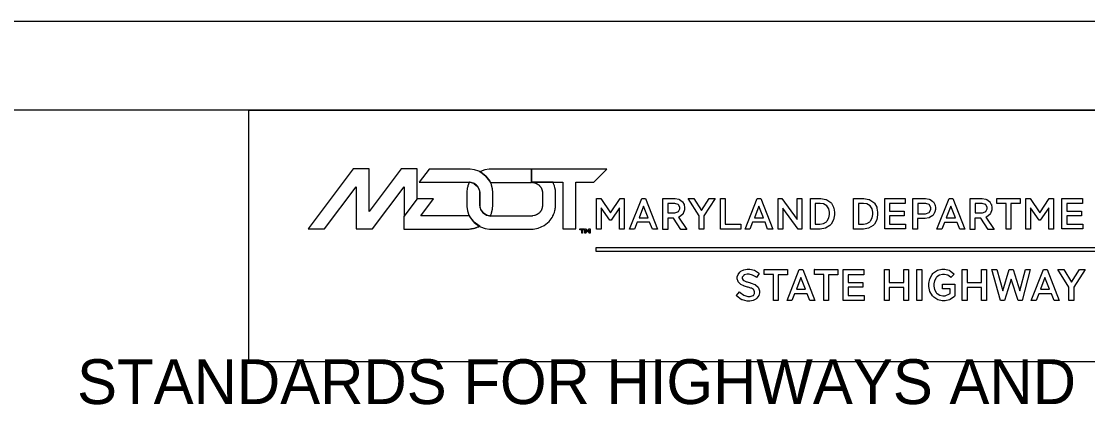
# Model space of a CAD drawing. Extents: x -0.5 to 19.9, y 5.2 to 17.3.
# Drawn here: x 15.428 to 17.634, y 6.826 to 7.619 of the extents above; entities that cross this region are included whole.
import ezdxf

# ---------------------------------------------------------------- set-up
doc = ezdxf.new("R2010")
doc.units = 0
for name, color, linetype in [('BORD-LINE', 7, 'Continuous'), ('MSHA-LOGO', 7, 'Continuous'), ('TTLB-TEXT', 7, 'Continuous'), ('USER-LINE', 7, 'Continuous')]:
    doc.layers.add(name, color=color, linetype=linetype)

msp = doc.modelspace()

# ---------------------------------------------------------------- linework, layer by layer
at = {"layer": 'BORD-LINE'}
for p, q in [((19.6208, 7.6193), (12.2466, 7.6193)), ((19.6208, 7.4352), (15.1479, 7.4352))]:
    msp.add_line(p, q, dxfattribs=at)
at = {"layer": 'MSHA-LOGO'}
for points in [[(16.2199, 7.2152), (16.247, 7.2513), (16.247, 7.314), (16.214, 7.314), (16.1936, 7.2866), (16.1478, 7.2255), (16.1478, 7.314), (16.1148, 7.314), (16.0216, 7.1897), (16.0556, 7.1897), (16.1206, 7.2765), (16.1206, 7.1897), (16.1548, 7.1897), (16.2199, 7.2765)], [(16.355, 7.2861), (16.3558, 7.2861), (16.3634, 7.2841), (16.3641, 7.2837), (16.365, 7.2833), (16.3687, 7.2805), (16.3719, 7.2772), (16.3725, 7.2765), (16.3731, 7.2756), (16.3753, 7.2709), (16.3765, 7.2658), (16.3766, 7.2648), (16.3766, 7.2648), (16.3766, 7.2646), (16.3766, 7.2646), (16.3766, 7.2643), (16.3766, 7.2637), (16.3766, 7.2635), (16.3766, 7.24), (16.3766, 7.2397), (16.3766, 7.2391), (16.3766, 7.2389), (16.3766, 7.2389), (16.3766, 7.2387), (16.3766, 7.2387), (16.3766, 7.2382), (16.3765, 7.2371), (16.3765, 7.2367), (16.3767, 7.2347), (16.3789, 7.2291), (16.3837, 7.2229), (16.3904, 7.2184), (16.3965, 7.2165), (16.3979, 7.2164), (16.3981, 7.2168), (16.3983, 7.217), (16.3983, 7.217), (16.3985, 7.2175), (16.4005, 7.2219), (16.4007, 7.2224), (16.4008, 7.2229), (16.4023, 7.2276), (16.4024, 7.2281), (16.4024, 7.2283), (16.403, 7.2307), (16.4031, 7.231), (16.4032, 7.2317), (16.4039, 7.238), (16.4039, 7.2401), (16.4039, 7.2632), (16.4039, 7.2655), (16.4032, 7.2716), (16.4031, 7.2723), (16.403, 7.2726), (16.4025, 7.275), (16.4024, 7.2753), (16.4023, 7.2757), (16.4008, 7.2805), (16.4007, 7.2809), (16.4005, 7.2814), (16.3985, 7.2859), (16.3983, 7.2863), (16.3971, 7.2886), (16.3891, 7.2988), (16.3789, 7.3068), (16.3766, 7.308), (16.3749, 7.3089), (16.3657, 7.3121), (16.3568, 7.3135), (16.3538, 7.3135), (16.2719, 7.3135), (16.2515, 7.2863), (16.3538, 7.2863), (16.3539, 7.2862), (16.3547, 7.2861)], [(16.3984, 7.2859), (16.3989, 7.2859), (16.3991, 7.2859), (16.4831, 7.2859), (16.4832, 7.2859), (16.4835, 7.2859), (16.4836, 7.2859), (16.4838, 7.2863), (16.4838, 7.3133), (16.4837, 7.3133), (16.4832, 7.3133), (16.4831, 7.3133), (16.3991, 7.3133), (16.3961, 7.3133), (16.3872, 7.3119), (16.378, 7.3087), (16.3766, 7.308), (16.3789, 7.3068), (16.3891, 7.2988), (16.3971, 7.2886), (16.3983, 7.2863)], [(16.4838, 7.3133), (16.4838, 7.2861), (16.5481, 7.2861), (16.5481, 7.1897), (16.5751, 7.1897), (16.5751, 7.2861), (16.6127, 7.2861), (16.6397, 7.3131), (16.6397, 7.3133)], [(16.3771, 7.1952), (16.3771, 7.1952), (16.3768, 7.1953), (16.3768, 7.1954), (16.3756, 7.196), (16.3653, 7.2035), (16.3644, 7.2045), (16.3635, 7.2054), (16.3561, 7.2156), (16.3555, 7.2167), (16.3554, 7.2167), (16.3551, 7.2167), (16.355, 7.2167), (16.3547, 7.2167), (16.354, 7.2167), (16.3538, 7.2167), (16.2544, 7.2167), (16.2808, 7.2517), (16.2468, 7.2517), (16.2197, 7.2157), (16.2197, 7.1895), (16.3536, 7.1895), (16.3544, 7.1895), (16.3565, 7.1896), (16.3567, 7.1897), (16.3574, 7.1897), (16.3594, 7.19), (16.3596, 7.19), (16.3598, 7.19), (16.3603, 7.1902), (16.3605, 7.1902), (16.3607, 7.1902), (16.3622, 7.1905), (16.3624, 7.1905), (16.3626, 7.1905), (16.3632, 7.1907), (16.3634, 7.1907), (16.3635, 7.1908), (16.365, 7.191), (16.3651, 7.191), (16.3652, 7.1911), (16.3661, 7.1914), (16.3662, 7.1914), (16.3663, 7.1914), (16.3676, 7.1919), (16.3677, 7.1919), (16.3678, 7.192), (16.3686, 7.1922), (16.3687, 7.1922), (16.3689, 7.1923), (16.3701, 7.1927), (16.3703, 7.1928), (16.3704, 7.1928), (16.3712, 7.1931), (16.3713, 7.1931), (16.3714, 7.1932), (16.3729, 7.1938), (16.373, 7.1938), (16.3731, 7.1938), (16.3738, 7.1941), (16.3739, 7.1942), (16.3741, 7.1942), (16.3761, 7.1952), (16.3763, 7.1954), (16.3764, 7.1953), (16.377, 7.1952)], [(16.6179, 7.2528), (16.6268, 7.2528), (16.6471, 7.2232), (16.6667, 7.2528), (16.6752, 7.2528), (16.6752, 7.1893), (16.6654, 7.1893), (16.6654, 7.2334), (16.6481, 7.2081), (16.6454, 7.2081), (16.6278, 7.2334), (16.6278, 7.1893), (16.6179, 7.1893)], [(16.7115, 7.2528), (16.7191, 7.2528), (16.7439, 7.1893), (16.7335, 7.1893), (16.7279, 7.2035), (16.702, 7.2035), (16.6965, 7.1893), (16.6863, 7.1893)], [(16.706, 7.2127), (16.7246, 7.2127), (16.7151, 7.2367)], [(16.7554, 7.189), (16.7554, 7.2525), (16.7776, 7.2525), (16.7804, 7.2525), (16.788, 7.2511), (16.7888, 7.2508), (16.7895, 7.2506), (16.7952, 7.2467), (16.7956, 7.2462), (16.796, 7.2457), (16.799, 7.2405), (16.7992, 7.24), (16.7994, 7.2394), (16.8002, 7.2342), (16.8002, 7.2324), (16.8002, 7.2295), (16.7975, 7.2217), (16.797, 7.2209), (16.7964, 7.2201), (16.7888, 7.2143), (16.7878, 7.214), (16.8048, 7.1886), (16.7927, 7.1886), (16.7773, 7.212), (16.7652, 7.212), (16.7652, 7.1886), (16.7554, 7.1886)], [(16.7652, 7.2423), (16.7652, 7.2229), (16.778, 7.2229), (16.7802, 7.2229), (16.7862, 7.2251), (16.7868, 7.2255), (16.7873, 7.2259), (16.7901, 7.2313), (16.7901, 7.2331), (16.7901, 7.2348), (16.7876, 7.2396), (16.7871, 7.24), (16.7866, 7.2404), (16.7799, 7.2423), (16.7776, 7.2423)], [(16.8401, 7.2166), (16.8401, 7.189), (16.8303, 7.189), (16.8303, 7.2166), (16.8074, 7.2528), (16.8195, 7.2528), (16.8352, 7.2275), (16.8513, 7.2528), (16.8631, 7.2528)], [(16.8742, 7.2528), (16.884, 7.2528), (16.884, 7.1995), (16.9164, 7.1995), (16.9164, 7.1893), (16.8742, 7.1893)], [(16.9501, 7.2528), (16.9576, 7.2528), (16.9825, 7.1893), (16.972, 7.1893), (16.9665, 7.2035), (16.9406, 7.2035), (16.935, 7.1893), (16.9252, 7.1893)], [(16.9445, 7.2127), (16.9632, 7.2127), (16.9537, 7.2367)], [(17.0349, 7.189), (17.0034, 7.2324), (17.0034, 7.189), (16.994, 7.189), (16.994, 7.2525), (17.0015, 7.2525), (17.0329, 7.2091), (17.0329, 7.2525), (17.0424, 7.2525), (17.0424, 7.189)], [(17.0604, 7.2528), (17.078, 7.2528), (17.0818, 7.2528), (17.092, 7.2509), (17.0931, 7.2505), (17.0942, 7.2501), (17.1026, 7.2443), (17.1033, 7.2436), (17.1038, 7.2429), (17.1082, 7.2346), (17.1085, 7.2337), (17.1087, 7.2328), (17.1101, 7.2246), (17.1101, 7.2219), (17.1101, 7.2186), (17.1081, 7.2088), (17.1033, 7.1998), (17.1019, 7.1982), (17.1005, 7.1967), (17.0916, 7.1915), (17.0807, 7.1893), (17.0771, 7.1893), (17.0604, 7.1893)], [(17.0702, 7.2423), (17.0702, 7.1995), (17.0777, 7.1995), (17.0802, 7.1995), (17.0875, 7.201), (17.0935, 7.2044), (17.0944, 7.2054), (17.0953, 7.2064), (17.0986, 7.2125), (17.1, 7.2195), (17.1, 7.2219), (17.1, 7.2242), (17.0986, 7.231), (17.0945, 7.2374), (17.0877, 7.2413), (17.0805, 7.2426), (17.078, 7.2426), (17.0702, 7.2426)], [(17.1497, 7.2528), (17.1674, 7.2528), (17.1711, 7.2528), (17.1814, 7.2509), (17.1824, 7.2505), (17.1835, 7.2501), (17.1919, 7.2443), (17.1926, 7.2436), (17.1931, 7.2429), (17.1976, 7.2346), (17.1978, 7.2337), (17.1981, 7.2328), (17.1995, 7.2246), (17.1995, 7.2219), (17.1995, 7.2186), (17.1975, 7.2088), (17.1927, 7.1998), (17.1913, 7.1982), (17.1899, 7.1967), (17.1809, 7.1915), (17.17, 7.1893), (17.1664, 7.1893), (17.1497, 7.1893)], [(17.1599, 7.2423), (17.1599, 7.1995), (17.1674, 7.1995), (17.1699, 7.1995), (17.1772, 7.201), (17.1832, 7.2044), (17.1841, 7.2054), (17.185, 7.2064), (17.1882, 7.2125), (17.1897, 7.2195), (17.1897, 7.2219), (17.1897, 7.2242), (17.1883, 7.231), (17.1842, 7.2374), (17.1773, 7.2413), (17.1701, 7.2426), (17.1677, 7.2426), (17.1599, 7.2426)], [(17.2142, 7.2528), (17.2564, 7.2528), (17.2564, 7.2426), (17.224, 7.2426), (17.224, 7.2265), (17.2544, 7.2265), (17.2544, 7.2166), (17.224, 7.2166), (17.224, 7.1998), (17.2574, 7.1998), (17.2574, 7.1896), (17.2142, 7.1896)], [(17.2724, 7.189), (17.2724, 7.2525), (17.2953, 7.2525), (17.2983, 7.2525), (17.3063, 7.2511), (17.3071, 7.2508), (17.3079, 7.2505), (17.3139, 7.2464), (17.3143, 7.2459), (17.3147, 7.2454), (17.3178, 7.2399), (17.3179, 7.2393), (17.3181, 7.2387), (17.3189, 7.2335), (17.3189, 7.2317), (17.3189, 7.2299), (17.3178, 7.2248), (17.3176, 7.2242), (17.3174, 7.2236), (17.3141, 7.2181), (17.3137, 7.2176), (17.3133, 7.2171), (17.307, 7.213), (17.3062, 7.2127), (17.3053, 7.2123), (17.2976, 7.211), (17.295, 7.211), (17.2819, 7.211), (17.2819, 7.1893), (17.2724, 7.1893)], [(17.2826, 7.2426), (17.2826, 7.2212), (17.2957, 7.2212), (17.2982, 7.2212), (17.306, 7.2239), (17.3094, 7.2301), (17.3094, 7.2321), (17.3094, 7.2341), (17.3062, 7.2399), (17.2988, 7.2426), (17.2963, 7.2426)], [(17.3474, 7.2528), (17.3549, 7.2528), (17.3798, 7.1893), (17.3693, 7.1893), (17.3637, 7.2031), (17.3379, 7.2031), (17.3323, 7.189), (17.3222, 7.189)], [(17.3415, 7.2127), (17.3602, 7.2127), (17.3507, 7.2367)], [(17.3909, 7.189), (17.3909, 7.2525), (17.4132, 7.2525), (17.4159, 7.2525), (17.4235, 7.2511), (17.4243, 7.2508), (17.425, 7.2506), (17.4307, 7.2467), (17.4312, 7.2462), (17.4316, 7.2457), (17.4345, 7.2405), (17.4348, 7.24), (17.4349, 7.2394), (17.4357, 7.2342), (17.4357, 7.2324), (17.4357, 7.2295), (17.433, 7.2217), (17.4325, 7.2209), (17.4319, 7.2201), (17.4243, 7.2143), (17.4233, 7.214), (17.4403, 7.1886), (17.4282, 7.1886), (17.4128, 7.212), (17.4007, 7.212), (17.4007, 7.1886), (17.3909, 7.1886)], [(17.4011, 7.2423), (17.4011, 7.2229), (17.4138, 7.2229), (17.416, 7.2229), (17.4221, 7.2251), (17.4227, 7.2255), (17.4231, 7.2259), (17.4259, 7.2313), (17.4259, 7.2331), (17.4259, 7.2348), (17.4235, 7.2396), (17.423, 7.24), (17.4225, 7.2404), (17.4157, 7.2423), (17.4135, 7.2423)], [(17.4462, 7.2528), (17.4943, 7.2528), (17.4943, 7.2426), (17.475, 7.2426), (17.475, 7.1893), (17.4652, 7.1893), (17.4652, 7.2426), (17.4462, 7.2426)], [(17.5058, 7.2528), (17.5146, 7.2528), (17.5349, 7.2232), (17.5545, 7.2528), (17.563, 7.2528), (17.563, 7.1893), (17.5532, 7.1893), (17.5532, 7.2334), (17.5359, 7.2081), (17.5333, 7.2081), (17.5156, 7.2334), (17.5156, 7.1893), (17.5058, 7.1893)], [(17.5807, 7.2528), (17.6229, 7.2528), (17.6229, 7.2426), (17.5905, 7.2426), (17.5905, 7.2265), (17.621, 7.2265), (17.621, 7.2166), (17.5905, 7.2166), (17.5905, 7.1998), (17.6239, 7.1998), (17.6239, 7.1896), (17.5807, 7.1896)], [(16.5837, 7.1897), (16.5926, 7.1897), (16.5926, 7.1881), (16.5892, 7.1881), (16.5892, 7.1807), (16.5874, 7.1807), (16.5874, 7.1881), (16.5837, 7.1881)], [(16.5938, 7.1897), (16.5955, 7.1897), (16.5993, 7.1853), (16.603, 7.1897), (16.6046, 7.1897), (16.6046, 7.1807), (16.6025, 7.1807), (16.6025, 7.1871), (16.5991, 7.183), (16.5957, 7.1871), (16.5957, 7.1807), (16.5938, 7.1807)], [(16.617, 7.151), (18.7337, 7.151), (18.7337, 7.1432), (16.617, 7.1432)], [(16.9431, 7.0638), (16.9428, 7.0641), (16.9385, 7.0667), (16.938, 7.067), (16.9374, 7.0671), (16.9316, 7.0691), (16.931, 7.0692), (16.9303, 7.0694), (16.9239, 7.0712), (16.9233, 7.0715), (16.9227, 7.0717), (16.9168, 7.0744), (16.9163, 7.0747), (16.9157, 7.075), (16.9115, 7.0796), (16.9112, 7.0801), (16.9108, 7.0807), (16.9092, 7.0866), (16.9092, 7.0885), (16.9092, 7.0902), (16.9109, 7.0955), (16.9146, 7.1005), (16.9156, 7.1013), (16.9167, 7.1022), (16.9228, 7.1052), (16.9296, 7.1065), (16.9319, 7.1065), (16.9351, 7.1065), (16.9447, 7.1041), (16.9529, 7.0987), (16.9543, 7.0972), (16.9489, 7.0891), (16.9477, 7.0903), (16.9409, 7.0942), (16.9339, 7.0959), (16.9316, 7.0959), (16.9294, 7.0959), (16.9235, 7.0943), (16.923, 7.0939), (16.9224, 7.0936), (16.9195, 7.0895), (16.9195, 7.0882), (16.9195, 7.0869), (16.9216, 7.0834), (16.922, 7.083), (16.9224, 7.0827), (16.928, 7.0803), (16.9287, 7.0801), (16.9294, 7.08), (16.9365, 7.0778), (16.9373, 7.0776), (16.9381, 7.0773), (16.9453, 7.0746), (16.946, 7.0744), (16.9466, 7.074), (16.9522, 7.0692), (16.9527, 7.0686), (16.9531, 7.0679), (16.9553, 7.0614), (16.9553, 7.0593), (16.9553, 7.0574), (16.9536, 7.0516), (16.9499, 7.0463), (16.9489, 7.0455), (16.9478, 7.0446), (16.9417, 7.0414), (16.9353, 7.04), (16.9332, 7.04), (16.9295, 7.04), (16.9197, 7.0427), (16.9185, 7.0432), (16.9173, 7.0438), (16.9083, 7.0508), (16.9076, 7.0516), (16.9137, 7.0593), (16.915, 7.0578), (16.9226, 7.0523), (16.9313, 7.05), (16.9342, 7.05), (16.9361, 7.05), (16.9417, 7.0516), (16.9421, 7.0519), (16.9426, 7.0522), (16.945, 7.0563), (16.945, 7.0577), (16.945, 7.0592), (16.9434, 7.0634)], [(16.9645, 7.1055), (17.0131, 7.1055), (17.0131, 7.0949), (16.9939, 7.0949), (16.9939, 7.0413), (16.984, 7.0413), (16.984, 7.0952), (16.9648, 7.0952), (16.9648, 7.1055)], [(17.037, 7.1055), (17.0447, 7.1055), (17.0699, 7.0413), (17.0594, 7.0413), (17.054, 7.0554), (17.0278, 7.0554), (17.0223, 7.0413), (17.0121, 7.0413)], [(17.0683, 7.1055), (17.1169, 7.1055), (17.1169, 7.0949), (17.0977, 7.0949), (17.0977, 7.0413), (17.0879, 7.0413), (17.0879, 7.0952), (17.0687, 7.0952), (17.0687, 7.1055)], [(17.1284, 7.1055), (17.1712, 7.1055), (17.1712, 7.0949), (17.1383, 7.0949), (17.1383, 7.0789), (17.169, 7.0789), (17.169, 7.0689), (17.1383, 7.0689), (17.1383, 7.0519), (17.1719, 7.0519), (17.1719, 7.0413), (17.1284, 7.0413)], [(17.2533, 7.0686), (17.2233, 7.0686), (17.2233, 7.0413), (17.2134, 7.0413), (17.2134, 7.1055), (17.2233, 7.1055), (17.2233, 7.0789), (17.2533, 7.0789), (17.2533, 7.1055), (17.2632, 7.1055), (17.2632, 7.0413), (17.2533, 7.0413)], [(17.2808, 7.1055), (17.2907, 7.1055), (17.2907, 7.0413), (17.2808, 7.0413)], [(17.3339, 7.0756), (17.3588, 7.0756), (17.3588, 7.0509), (17.3581, 7.0501), (17.3498, 7.0439), (17.3489, 7.0435), (17.3478, 7.0431), (17.339, 7.041), (17.3361, 7.041), (17.333, 7.041), (17.3239, 7.0432), (17.3155, 7.0484), (17.314, 7.05), (17.3126, 7.0515), (17.3076, 7.0604), (17.3054, 7.0704), (17.3054, 7.0737), (17.3054, 7.0769), (17.3075, 7.0865), (17.3124, 7.0956), (17.3137, 7.0972), (17.3152, 7.0988), (17.3233, 7.1042), (17.3319, 7.1065), (17.3348, 7.1065), (17.3382, 7.1065), (17.3472, 7.1041), (17.3482, 7.1036), (17.3492, 7.1031), (17.3569, 7.0967), (17.3575, 7.0959), (17.3508, 7.0888), (17.3499, 7.0899), (17.3443, 7.0939), (17.3377, 7.0956), (17.3355, 7.0956), (17.3334, 7.0956), (17.3273, 7.0941), (17.322, 7.0905), (17.3211, 7.0894), (17.3202, 7.0885), (17.317, 7.0825), (17.3156, 7.0757), (17.3156, 7.0734), (17.3156, 7.0711), (17.3171, 7.0641), (17.3204, 7.0581), (17.3214, 7.057), (17.3224, 7.0561), (17.3279, 7.0527), (17.334, 7.0512), (17.3361, 7.0512), (17.3394, 7.0512), (17.3483, 7.055), (17.3492, 7.0557), (17.3492, 7.0657), (17.3339, 7.0657)], [(17.4144, 7.0686), (17.3843, 7.0686), (17.3843, 7.0413), (17.3744, 7.0413), (17.3744, 7.1055), (17.3843, 7.1055), (17.3843, 7.0789), (17.4144, 7.0789), (17.4144, 7.1055), (17.4243, 7.1055), (17.4243, 7.0413), (17.4144, 7.0413)], [(17.4981, 7.0413), (17.4898, 7.0413), (17.4757, 7.0859), (17.462, 7.0413), (17.4537, 7.0413), (17.4358, 7.1055), (17.446, 7.1055), (17.4581, 7.0612), (17.4716, 7.1055), (17.4796, 7.1055), (17.4933, 7.0612), (17.5051, 7.1055), (17.515, 7.1055)], [(17.5422, 7.1055), (17.5499, 7.1055), (17.5751, 7.0413), (17.5646, 7.0413), (17.5588, 7.0554), (17.5326, 7.0554), (17.5272, 7.0413), (17.5169, 7.0413)], [(17.6051, 7.0692), (17.6051, 7.0413), (17.5952, 7.0413), (17.5952, 7.0692), (17.5722, 7.1055), (17.5847, 7.1055), (17.6007, 7.0798), (17.617, 7.1055), (17.6288, 7.1055)], [(17.0313, 7.065), (17.0501, 7.065), (17.0406, 7.0894)], [(17.5361, 7.065), (17.555, 7.065), (17.5454, 7.0894)]]:
    msp.add_lwpolyline(points, close=True, dxfattribs=at)
for points in [[(16.3766, 7.2503), (16.3766, 7.2632), (16.3766, 7.2636), (16.3766, 7.2643), (16.3766, 7.2646), (16.3766, 7.2651), (16.3768, 7.2663), (16.3768, 7.2667), (16.3767, 7.2676), (16.3734, 7.2759), (16.3729, 7.2766), (16.3723, 7.2774), (16.369, 7.2809), (16.3651, 7.2836), (16.3643, 7.284), (16.3635, 7.2844), (16.356, 7.2864), (16.3552, 7.2865), (16.3552, 7.2864), (16.355, 7.2861), (16.3546, 7.2855), (16.352, 7.2787), (16.3517, 7.278), (16.3516, 7.2778), (16.351, 7.2754), (16.3509, 7.2751), (16.3507, 7.2741), (16.3495, 7.2659), (16.3495, 7.2632), (16.3495, 7.2503), (16.3495, 7.2489)], [(16.5334, 7.2632), (16.5334, 7.2639), (16.5333, 7.2659), (16.5332, 7.2661), (16.5332, 7.2663), (16.5332, 7.267), (16.5332, 7.2675), (16.533, 7.2687), (16.533, 7.2691), (16.533, 7.2692), (16.533, 7.2695), (16.533, 7.2696), (16.533, 7.2697), (16.533, 7.2699), (16.533, 7.2699), (16.533, 7.2701), (16.5327, 7.2718), (16.5327, 7.272), (16.5327, 7.2722), (16.5325, 7.2726), (16.5325, 7.2727), (16.5325, 7.2729), (16.5321, 7.2747), (16.532, 7.2749), (16.532, 7.2751), (16.532, 7.2753), (16.5319, 7.2755), (16.5312, 7.2781), (16.5312, 7.2784), (16.531, 7.2788), (16.5294, 7.2831), (16.5293, 7.2835), (16.5292, 7.2837), (16.5281, 7.2859), (16.5281, 7.2861), (16.5281, 7.2862), (16.5279, 7.2865), (16.4845, 7.2865), (16.4843, 7.2861), (16.4848, 7.2861), (16.485, 7.2861), (16.4852, 7.2861), (16.4857, 7.286), (16.4858, 7.2859), (16.4862, 7.2859), (16.4896, 7.2852), (16.49, 7.2851), (16.4902, 7.285), (16.4931, 7.284), (16.4934, 7.2839), (16.4936, 7.2838), (16.4951, 7.2829), (16.4953, 7.2828), (16.4954, 7.2828), (16.4954, 7.2828), (16.4956, 7.2828), (16.497, 7.2819), (16.4972, 7.2818), (16.4973, 7.2817), (16.4973, 7.2816), (16.4975, 7.2815), (16.4987, 7.2806), (16.4989, 7.2804), (16.499, 7.2803), (16.4992, 7.2802), (16.5002, 7.2791), (16.5003, 7.279), (16.5004, 7.2789), (16.5004, 7.2789), (16.5006, 7.2787), (16.5007, 7.2786), (16.5014, 7.2778), (16.5015, 7.2777), (16.5016, 7.2775), (16.5017, 7.2775), (16.5019, 7.277), (16.502, 7.277), (16.5021, 7.2769), (16.5028, 7.2759), (16.5028, 7.2758), (16.5029, 7.2757), (16.5031, 7.2752), (16.5032, 7.2751), (16.5033, 7.2749), (16.5033, 7.2749), (16.5034, 7.2748), (16.5038, 7.274), (16.5039, 7.2739), (16.5039, 7.2738), (16.5042, 7.2731), (16.5042, 7.273), (16.5042, 7.2729), (16.5047, 7.2719), (16.5047, 7.2718), (16.5048, 7.2718), (16.5049, 7.2711), (16.5049, 7.271), (16.505, 7.2708), (16.5051, 7.2708), (16.5051, 7.2707), (16.5054, 7.27), (16.5054, 7.2697), (16.5054, 7.2697), (16.5057, 7.2686), (16.5057, 7.2685), (16.5057, 7.2683), (16.5059, 7.2677), (16.5059, 7.2675), (16.506, 7.2674), (16.5061, 7.2664), (16.5061, 7.2661), (16.5061, 7.2659), (16.5063, 7.2654), (16.5063, 7.2653), (16.5063, 7.2647), (16.5064, 7.2635), (16.5064, 7.263), (16.5064, 7.2394), (16.5064, 7.2389), (16.5063, 7.2374), (16.5063, 7.2372), (16.5063, 7.237), (16.5061, 7.2364), (16.5061, 7.2363), (16.5061, 7.236), (16.5059, 7.2352), (16.5059, 7.235), (16.5059, 7.2347), (16.5057, 7.2341), (16.5057, 7.2339), (16.5057, 7.2338), (16.5054, 7.2328), (16.5054, 7.2327), (16.5054, 7.2326), (16.5051, 7.2318), (16.5051, 7.2317), (16.5051, 7.2316), (16.5049, 7.2314), (16.5049, 7.2313), (16.5047, 7.2308), (16.5047, 7.2307), (16.5047, 7.2306), (16.5042, 7.2296), (16.5042, 7.2295), (16.5042, 7.2294), (16.5039, 7.2287), (16.5039, 7.2286), (16.5038, 7.2285), (16.5034, 7.2276), (16.5033, 7.2276), (16.5032, 7.2274), (16.5032, 7.2274), (16.5031, 7.2273), (16.5029, 7.2268), (16.5028, 7.2267), (16.5027, 7.2266), (16.5021, 7.2256), (16.502, 7.2255), (16.5019, 7.2255), (16.5017, 7.225), (16.5016, 7.225), (16.5015, 7.2248), (16.5014, 7.2247), (16.5006, 7.2239), (16.5006, 7.2238), (16.5004, 7.2236), (16.5003, 7.2234), (16.5003, 7.2234), (16.5002, 7.2233), (16.4991, 7.2223), (16.499, 7.2222), (16.4989, 7.222), (16.4987, 7.222), (16.4975, 7.2209), (16.4973, 7.2208), (16.4972, 7.2207), (16.4972, 7.2207), (16.497, 7.2206), (16.4956, 7.2197), (16.4954, 7.2196), (16.4953, 7.2196), (16.4953, 7.2196), (16.4951, 7.2196), (16.4936, 7.2187), (16.4934, 7.2186), (16.4931, 7.2185), (16.4902, 7.2175), (16.49, 7.2174), (16.4896, 7.2173), (16.4862, 7.2166), (16.4858, 7.2165), (16.4856, 7.2165), (16.4851, 7.2164), (16.485, 7.2164), (16.4847, 7.2164), (16.484, 7.2164), (16.4838, 7.2164), (16.3998, 7.2164), (16.3995, 7.2164), (16.3988, 7.2164), (16.3986, 7.2164), (16.3965, 7.2165), (16.3904, 7.2184), (16.3837, 7.2231), (16.379, 7.2298), (16.3771, 7.2358), (16.377, 7.2379), (16.377, 7.2382), (16.377, 7.239), (16.377, 7.2393), (16.377, 7.2503), (16.3766, 7.2503)], [(16.3495, 7.2489), (16.3495, 7.2393), (16.3495, 7.2363), (16.351, 7.2273), (16.3541, 7.2181), (16.355, 7.2164), (16.3556, 7.2152), (16.3632, 7.2047), (16.3641, 7.2038), (16.365, 7.2029), (16.3755, 7.1953), (16.3766, 7.1947), (16.3784, 7.1938), (16.3875, 7.1906), (16.3965, 7.1892), (16.3995, 7.1892), (16.4834, 7.1892), (16.4869, 7.1892), (16.4974, 7.1911), (16.5098, 7.1967), (16.5201, 7.2053), (16.5263, 7.2134), (16.5279, 7.2164), (16.528, 7.2166), (16.529, 7.2187), (16.5291, 7.2189), (16.5293, 7.2194), (16.5308, 7.2237), (16.531, 7.2241), (16.5311, 7.2244), (16.5318, 7.227), (16.5318, 7.2272), (16.5318, 7.2274), (16.5318, 7.2276), (16.5319, 7.2277), (16.5323, 7.2296), (16.5324, 7.2298), (16.5324, 7.23), (16.5325, 7.2304), (16.5325, 7.2305), (16.5326, 7.2307), (16.5328, 7.2324), (16.5329, 7.2325), (16.5329, 7.2326), (16.5329, 7.2328), (16.5329, 7.2329), (16.5329, 7.233), (16.5329, 7.2333), (16.5329, 7.2334), (16.5329, 7.2339), (16.533, 7.2351), (16.533, 7.2355), (16.533, 7.2362), (16.533, 7.2363), (16.533, 7.2371), (16.5332, 7.2387), (16.5332, 7.2393), (16.5334, 7.2632)]]:
    msp.add_lwpolyline(points, dxfattribs=at)
at = {"layer": 'USER-LINE'}
msp.add_lwpolyline([(18.8699, 6.9145), (15.8988, 6.9145), (15.8988, 7.4352), (18.8699, 7.4352)], close=True, dxfattribs=at)

# ---------------------------------------------------------------- texts
at = {"layer": 'TTLB-TEXT'}
msp.add_text('STANDARDS FOR HIGHWAYS AND INCIDENTAL STRUCTURES', height=0.09269, dxfattribs=at).set_placement((15.5437, 6.8272))

doc.saveas('drawing.dxf')
